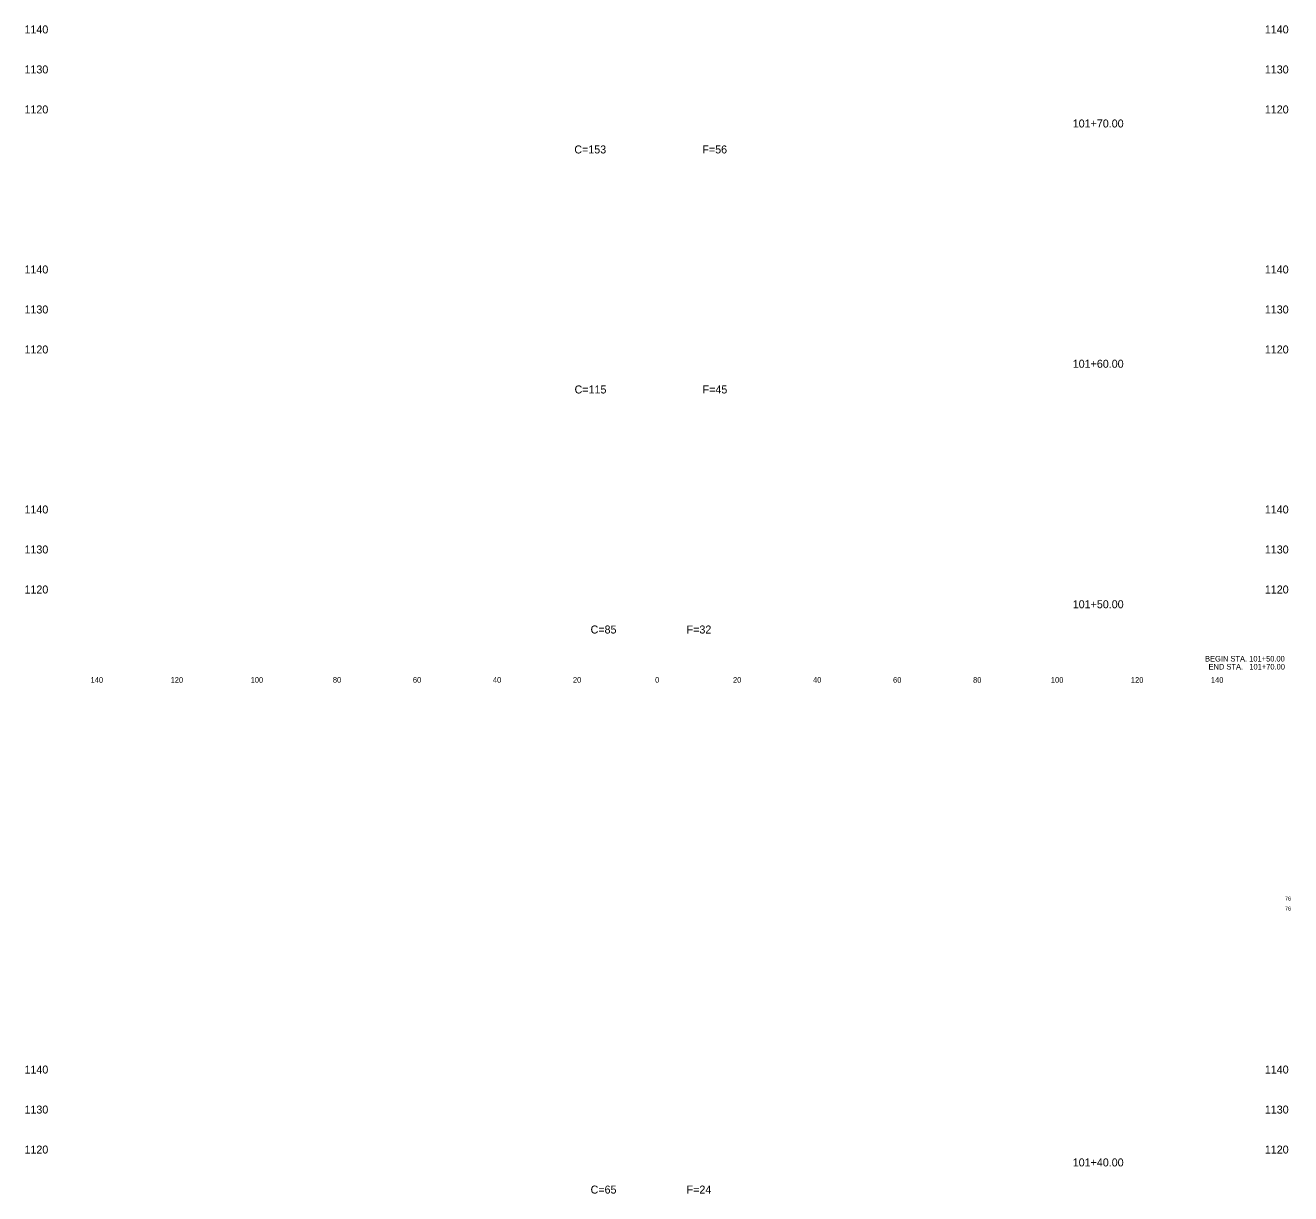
# Model space of a CAD drawing. Extents: x -200 to 1318, y -200 to 2244.
# Drawn here: x 1001.9 to 1318.2, y 1650 to 1942 of the extents above; entities that cross this region are included whole.
import ezdxf

# ---------------------------------------------------------------- set-up
doc = ezdxf.new("R2010")
doc.units = 0
for name, color, linetype in [('Default', 7, 'Continuous'), ('DESIGN - SHEET - Corner Text', 7, 'Continuous'), ('DESIGN - TYPICAL - Text', 7, 'Continuous')]:
    doc.layers.add(name, color=color, linetype=linetype)

msp = doc.modelspace()

# ---------------------------------------------------------------- texts
at = {"layer": 'Default'}
for s, height, p in [('     1140     ', 2, (998.01, 1940)), ('     1140     ', 2, (1308.01, 1940)), ('     1130     ', 2, (998.01, 1930)), ('     1130     ', 2, (1308.01, 1930)), ('     1120     ', 2, (998.01, 1920)), ('     1120     ', 2, (1308.01, 1920)), ('     101+70.00     ', 2, (1260, 1916.49)), ('     1140     ', 2, (998.01, 1880)), ('     1140     ', 2, (1308.01, 1880)), ('     1130     ', 2, (998.01, 1870)), ('     1130     ', 2, (1308.01, 1870)), ('     1120     ', 2, (998.01, 1860)), ('     1120     ', 2, (1308.01, 1860)), ('     101+60.00     ', 2, (1260, 1856.43)), ('     1140     ', 2, (998.01, 1820)), ('     1140     ', 2, (1308.01, 1820)), ('     1130     ', 2, (998.01, 1810)), ('     1130     ', 2, (1308.01, 1810)), ('     1120     ', 2, (998.01, 1800)), ('     1120     ', 2, (1308.01, 1800)), ('     101+50.00     ', 2, (1260, 1796.31)), ('     140     ', 1.4, (1015.65, 1777.7)), ('     120     ', 1.4, (1035.65, 1777.7)), ('     100     ', 1.4, (1055.65, 1777.7)), ('     80     ', 1.4, (1076.2, 1777.7)), ('     60     ', 1.4, (1096.2, 1777.7)), ('     40     ', 1.4, (1116.2, 1777.7)), ('     20     ', 1.4, (1136.2, 1777.7)), ('     0     ', 1.4, (1156.74, 1777.7)), ('     0     ', 1.4, (1156.74, 1777.7)), ('     20     ', 1.4, (1176.2, 1777.7)), ('     40     ', 1.4, (1196.2, 1777.7)), ('     60     ', 1.4, (1216.2, 1777.7)), ('     80     ', 1.4, (1236.2, 1777.7)), ('     100     ', 1.4, (1255.65, 1777.7)), ('     120     ', 1.4, (1275.65, 1777.7)), ('     140     ', 1.4, (1295.65, 1777.7)), ('     1140     ', 2, (998.01, 1680)), ('     1140     ', 2, (1308.01, 1680)), ('     1130     ', 2, (998.01, 1670)), ('     1130     ', 2, (1308.01, 1670)), ('     1120     ', 2, (998.01, 1660)), ('     1120     ', 2, (1308.01, 1660)), ('     101+40.00     ', 2, (1260, 1656.79))]:
    msp.add_text(s, height=height, dxfattribs=at).set_placement(p)
at = {"layer": 'DESIGN - SHEET - Corner Text'}
for s, height, p in [('BEGIN STA. 101+50.00', 1.4, (1296.78, 1783)), ('END STA.   101+70.00', 1.4, (1297.65, 1781)), ('76', 1, (1316.75, 1723.25)), ('76', 1, (1316.75, 1720.75))]:
    msp.add_text(s, height=height, dxfattribs=at).set_placement(p)
at = {"layer": 'DESIGN - TYPICAL - Text'}
for s, p in [('C=153', (1139.15, 1910)), ('F=56', (1171.15, 1910)), ('C=115', (1139.21, 1850)), ('F=45', (1171.21, 1850)), ('C=85', (1143.21, 1790)), ('F=32', (1167.21, 1790)), ('C=65', (1143.21, 1650)), ('F=24', (1167.21, 1650))]:
    msp.add_text(s, height=2, dxfattribs=at).set_placement(p)

doc.saveas('drawing.dxf')
